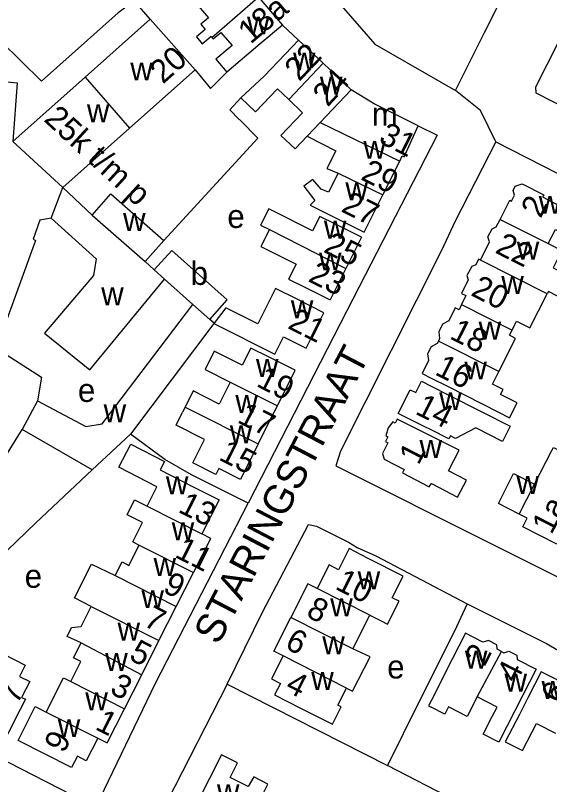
# Model space of a CAD drawing. Extents: x 159700 to 161346, y 381730 to 382922.
# Drawn here: x 160928.7 to 161020.3, y 382436.1 to 382568 of the extents above; entities that cross this region are included whole.
import ezdxf

# ---------------------------------------------------------------- set-up
doc = ezdxf.new("R2010")
doc.units = 0
for name, color, linetype in [('BLT_Basislijn', 7, 'Continuous'), ('BLT_Bebouwing', 7, 'Continuous'), ('BLT_Centroide', 7, 'Continuous'), ('BLT_Huisnummer', 7, 'Continuous'), ('BLT_Huisnummer_ tussenligend', 7, 'Continuous'), ('BLT_Huisnummer_reeks', 7, 'Continuous'), ('BLT_Onderverdeling_panden', 7, 'Continuous'), ('BLT_Straatnaam', 7, 'Continuous')]:
    doc.layers.add(name, color=color, linetype=linetype)

msp = doc.modelspace()

# ---------------------------------------------------------------- linework, layer by layer
at = {"layer": 'BLT_Basislijn'}
for p, q in [((160974.51, 382566.37), (160977.27, 382563.79)), ((161007.45, 382561.69), (161009.16, 382565.09)), ((161004.18, 382555.15), (161007.45, 382561.69)), ((160970.27, 382546.97), (160954.17, 382529.44)), ((160932.23, 382481.02), (160941.86, 382490.1)), ((160932.23, 382481.02), (160912.18, 382461.91)), ((160965.01, 382453.32), (160992.5, 382439.39))]:
    msp.add_line(p, q, dxfattribs=at)
for points in [[(161009.16, 382565.09), (161014.49, 382575.65), (161032.79, 382593.12), (161036.12, 382596.65), (161036.59, 382596.65), (161044.04, 382603.72), (161044.42, 382604.08)], [(160951.83, 382567.37), (160949.25, 382570.37), (160948.92, 382570.37), (160946.35, 382568.47), (160933.21, 382556.75), (160926.24, 382563.59)], [(160983.2, 382571.05), (160984.24, 382570.15), (160990.35, 382563.1), (161004.18, 382555.15)], [(161024.71, 382568.32), (161023.67, 382567.09), (161017.93, 382555.74), (161017.98, 382554.76), (161074.53, 382525.9), (161075.55, 382526.06), (161075.87, 382526.38), (161077.62, 382529.86)], [(160959.55, 382558.7), (160962.18, 382555.47), (160964.96, 382558.3)], [(160919.62, 382557.35), (160929.02, 382556.44), (160928.26, 382546.4)], [(161011.13, 382546.35), (161008.45, 382551.7), (161004.18, 382555.15)], [(160970.27, 382546.97), (160967.2, 382550.09), (160967.09, 382550.2), (160965.47, 382551.85), (160967.35, 382553.88)], [(160997.77, 382549.07), (161001.05, 382547.46), (160985.55, 382517.37), (160968.62, 382484.37)], [(161011.13, 382546.35), (161004.14, 382532.72), (161001.78, 382527.68), (160984.45, 382493.29), (160983.66, 382490.77), (161037.03, 382464.02), (161097.28, 382433.33), (161117.83, 382422.87), (161120.84, 382421.08), (161151.41, 382405.63), (161152.84, 382405.02), (161153.31, 382404.99), (161153.57, 382405.21), (161167.8, 382433.33), (161179.15, 382454.6), (161181.26, 382459.06), (161181.21, 382459.73), (161169.51, 382465.52), (161164.37, 382468.48), (161163.6, 382468.73), (161139.77, 382480.75)], [(161011.13, 382546.35), (161059.35, 382521.71), (161069.03, 382516.96), (161080.74, 382510.81), (161104.09, 382499.08), (161138.78, 382481.25), (161139.77, 382480.75)], [(160934.87, 382533.23), (160932.92, 382532.91), (160931.78, 382529.63), (160932.15, 382529.42), (160927.26, 382515.85), (160921.38, 382518.08)], [(160918.77, 382514.15), (160926.98, 382509.98), (160933.19, 382505.98), (160932.52, 382501.95)], [(160919.1, 382489.6), (160924.73, 382488.77), (160929.87, 382497)], [(160968.62, 382484.37), (160958.93, 382489.25), (160954.36, 382491.88), (160948.48, 382496.22)], [(160925.44, 382441), (160942.54, 382432.23), (160952.75, 382453.52), (160968.62, 382484.37)], [(160965.01, 382453.32), (160971.12, 382465.68), (160978.98, 382480.7), (160980.37, 382480.41), (160985.86, 382477.68), (160987.34, 382476.75), (160990.51, 382475.36), (161006.2, 382467.14)], [(161006.2, 382467.14), (161004, 382462.43), (160997.96, 382450.36), (160992.5, 382439.39)], [(161006.2, 382467.14), (161019.79, 382460.32), (161025.02, 382457.3), (161053.5, 382442.94), (161053.96, 382442.53), (161071.63, 382433.33), (161121.07, 382408.34)], [(160965.01, 382453.32), (160954.82, 382433.33), (160951.71, 382427.25), (160951.57, 382426.07), (160951.73, 382425.91), (161001.45, 382400.93), (161003.57, 382399.63), (161024.09, 382389.46), (161033.76, 382384.37), (161056.56, 382372.91)], [(161070.21, 382399.65), (161041.47, 382414.49), (161034.11, 382417.92), (161004.24, 382433.33), (160992.5, 382439.39)]]:
    msp.add_lwpolyline(points, dxfattribs=at)
at = {"layer": 'BLT_Bebouwing'}
for p, q in [((160970.39, 382571.19), (160974.51, 382566.37)), ((160940.68, 382557.44), (160951.83, 382567.37)), ((160951.83, 382567.37), (160959.55, 382558.7)), ((160981.47, 382559.81), (160977.27, 382563.79)), ((160986.28, 382555.24), (160981.47, 382559.81)), ((160959.55, 382558.7), (160948.26, 382548.66)), ((160928.26, 382546.4), (160940.68, 382557.44)), ((160948.26, 382548.66), (160936.84, 382538.5)), ((160936.84, 382538.5), (160928.26, 382546.4)), ((160991.72, 382537.23), (160994.62, 382543.03)), ((160934.87, 382533.23), (160936.84, 382538.5)), ((160941.9, 382533.77), (160945.07, 382537.4)), ((160945.07, 382537.4), (160954.17, 382529.44)), ((160988.54, 382530.86), (160991.72, 382537.23)), ((160954.17, 382529.44), (160951, 382525.81)), ((160988.09, 382529.97), (160985.41, 382524.6)), ((160952.52, 382524.37), (160951, 382525.81)), ((160985.41, 382524.6), (160982.72, 382519.24)), ((160941.46, 382507.22), (160954.3, 382522.78)), ((160954.3, 382522.78), (160959.15, 382518.46)), ((161016.95, 382514.44), (161019.9, 382520.27)), ((160962.06, 382515.86), (160965.06, 382519.22)), ((160962.76, 382515.19), (160948.48, 382496.22)), ((160962.78, 382515.22), (160962.06, 382515.86)), ((160933.71, 382513.56), (160941.46, 382507.22)), ((160932.52, 382501.95), (160929.87, 382497)), ((160957.83, 382500.86), (160957.4, 382500)), ((160973.1, 382500), (160973.64, 382501.07)), ((160970.37, 382494.53), (160973.1, 382500)), ((160941.86, 382490.1), (160929.87, 382497)), ((160948.48, 382496.22), (160941.86, 382490.1)), ((160948.86, 382477.75), (160949.95, 382477.19)), ((160956.29, 382466.64), (160959.25, 382472.49)), ((160953.33, 382460.8), (160956.29, 382466.64)), ((160986.56, 382459.41), (160989.48, 382465.18)), ((160950.38, 382454.95), (160953.33, 382460.8)), ((160934, 382448.55), (160936.96, 382454.4)), ((160936.96, 382454.4), (160938.2, 382453.78)), ((160947.42, 382449.11), (160950.38, 382454.95)), ((160932.12, 382449.51), (160934, 382448.55))]:
    msp.add_line(p, q, dxfattribs=at)
for points in [[(160959.36, 382570.44), (160961.81, 382567.58), (160960.54, 382566.5), (160961.28, 382565.62), (160959.76, 382564.34), (160960.76, 382563.15), (160962.28, 382564.44), (160962.43, 382564.26)], [(160974.51, 382566.37), (160970.69, 382563.14), (160964.96, 382558.3)], [(160962.43, 382564.26), (160962.64, 382564.02), (160963.96, 382565.12)], [(160963.96, 382565.12), (160965.87, 382562.89), (160963.08, 382560.5), (160964.96, 382558.3)], [(160977.27, 382563.79), (160973.83, 382560.17), (160971.39, 382557.59), (160967.35, 382553.88)], [(160967.35, 382553.88), (160969.87, 382551.49), (160973.64, 382555.46), (160975.59, 382553.6)], [(160997.77, 382549.07), (160990.24, 382552.87), (160986.28, 382555.24)], [(160975.59, 382553.61), (160977.98, 382551.34), (160974.26, 382547.42), (160976.68, 382545.12), (160978.76, 382547.32)], [(160994.62, 382543.03), (160995.07, 382543.92), (160995.41, 382543.75), (160997.77, 382549.07)], [(160978.76, 382547.32), (160978.86, 382547.23), (160983.67, 382544.81), (160982.12, 382541.75), (160984.07, 382540.98)], [(160984.07, 382540.98), (160982.42, 382537.71), (160981.14, 382538.24), (160979.71, 382539.91), (160978.19, 382538.73), (160980.08, 382536.3), (160979.28, 382535.49), (160984.07, 382533.1), (160988.54, 382530.86)], [(161011.84, 382533.05), (161013.49, 382536.33), (161013.78, 382536.18), (161014.28, 382537.17), (161014.07, 382538.01), (161014.44, 382538.74), (161015.62, 382539.12), (161019.32, 382537.28), (161019.11, 382536.9), (161028.1, 382532.15)], [(160941.9, 382533.77), (160936.84, 382538.5)], [(160975.17, 382533.37), (160972.17, 382534.88), (160970.75, 382532.08), (160972.27, 382531.31)], [(160988.09, 382529.97), (160983.62, 382532.21), (160980.94, 382533.55), (160979.69, 382531.08), (160977.49, 382532.19), (160975.17, 382533.37)], [(160934.87, 382533.23), (160942.58, 382526.29), (160942.12, 382523.41), (160933.71, 382513.56)], [(161008.45, 382526.05), (161010.04, 382529.2), (161009.75, 382530.04), (161010.46, 382531.45), (161011.18, 382531.74), (161011.84, 382533.05)], [(161020.1, 382528.88), (161021.33, 382531.32), (161024.39, 382529.77), (161024.67, 382530.32), (161026.69, 382529.3), (161028.1, 382532.15)], [(160972.27, 382531.31), (160970.8, 382528.41)], [(160970.8, 382528.41), (160976.85, 382525.35), (160975.57, 382522.81), (160978.25, 382521.47), (160982.72, 382519.24)], [(161020.1, 382528.88), (161022.43, 382527.7), (161020.92, 382524.73), (161024.68, 382522.82), (161022.89, 382519.27), (161020.11, 382520.68), (161019.9, 382520.27)], [(160965.06, 382519.22), (160955.52, 382527.73), (160952.52, 382524.37)], [(161008.45, 382526.05), (161008.14, 382526.21), (161007.67, 382525.26), (161006.97, 382524.99), (161006.16, 382523.43), (161006.36, 382522.65), (161005.21, 382520.35), (161005.96, 382519.97), (161005.21, 382518.43)], [(160981.63, 382517.04), (160977.15, 382519.28), (160973.33, 382521.2), (160970.29, 382515.12), (160964.78, 382517.87), (160962.78, 382515.22)], [(160932.52, 382501.95), (160940.79, 382497.53), (160943.58, 382497.96), (160959.15, 382518.46)], [(161005.21, 382518.43), (161004.79, 382517.55), (161004.14, 382517.87), (161003.02, 382515.67), (161001.96, 382515.05), (161001.32, 382513.78), (161001.47, 382512.59), (161001.26, 382512.18)], [(160962.76, 382515.19), (160973.23, 382509.95), (160974.7, 382512.9), (160978.58, 382510.96), (160981.63, 382517.04)], [(161013.88, 382514.06), (161014.66, 382515.6), (161016.95, 382514.44)], [(161011.62, 382506.95), (161014.5, 382512.64), (161013.43, 382513.18), (161013.88, 382514.06)], [(161001.26, 382512.18), (161001.05, 382511.77), (161000, 382511.17), (160999.39, 382509.97), (160999.58, 382508.86), (160998.45, 382506.62), (161000, 382505.84), (161002.91, 382504.36), (161011.55, 382500), (161013.46, 382499.03), (161014.76, 382501.6), (161011.92, 382503.04), (161012.34, 382503.86), (161010.52, 382504.78), (161011.62, 382506.95)], [(160973.64, 382501.07), (160976.68, 382507.16), (160972.21, 382509.4), (160969.07, 382510.97), (160967.58, 382508.02), (160962.83, 382510.42), (160961.26, 382507.32), (160965.57, 382505.14)], [(160965.57, 382505.14), (160963.67, 382501.37), (160959.23, 382503.62), (160957.83, 382500.86)], [(160994.47, 382500), (160996.41, 382503.84), (160997.37, 382503.35), (160998.35, 382505.29), (161000, 382504.46), (161002.81, 382503.04), (161008.82, 382500), (161013.58, 382497.6), (161012.23, 382494.97), (161007.68, 382497.31), (161004.21, 382495.47), (161003.32, 382495.93), (161003.05, 382495.39), (161000, 382496.93)], [(160970.37, 382494.53), (160967.3, 382488.45), (160963.61, 382490.32), (160963.1, 382489.29), (160959.14, 382491.27), (160961.15, 382495.29), (160956.28, 382497.75), (160957.4, 382500)], [(161000, 382496.93), (160998.82, 382497.53), (160994.36, 382499.78), (160994.47, 382500)], [(161000, 382495.87), (160998.65, 382496.55), (160994.19, 382498.8), (160993.83, 382498.11), (160993.46, 382498.3), (160992.63, 382497.3), (160992.27, 382495.91), (160992.59, 382495.74), (160992.18, 382494.93), (160992.61, 382494.71), (160991.67, 382492.87), (160991.97, 382491.93), (160995.4, 382490.16), (160995.09, 382489.56), (160999.7, 382487.18), (161000, 382487.67)], [(161000, 382487.67), (161000.05, 382487.76), (161004.56, 382485.43), (161006.05, 382488.33), (161003, 382489.92), (161004.81, 382493.44), (161000, 382495.87)], [(160951.29, 382483.86), (160952.98, 382487.19), (160946.45, 382490.58), (160948.49, 382494.48), (160954.27, 382491.54), (160953.52, 382490.07), (160959.18, 382487.18), (160963.64, 382484.93), (160960.69, 382479.1)], [(161017.74, 382487.61), (161020.7, 382493.39), (161020.98, 382493.95), (161028.16, 382490.32), (161026.07, 382486.23)], [(161015.12, 382482.5), (161011.55, 382484.33), (161014.16, 382489.44), (161017.74, 382487.61)], [(161026.07, 382486.23), (161023.82, 382481.81), (161021.54, 382477.36), (161015.75, 382480.34), (161016.5, 382481.8), (161015.12, 382482.5)], [(160948.86, 382477.75), (160950.53, 382481.06), (160947.86, 382482.36), (160949.12, 382484.94), (160951.29, 382483.86)], [(160959.25, 382472.49), (160962.21, 382478.33), (160960.69, 382479.1)], [(160945.81, 382471.95), (160947, 382474.29), (160948.18, 382473.69), (160949.95, 382477.19)], [(160989.48, 382465.18), (160991.34, 382464.26), (160992.55, 382463.63), (160994.52, 382467.55), (160993.32, 382468.16), (160995.21, 382471.88), (160989.23, 382474.91), (160985.94, 382476.58), (160985.08, 382474.88), (160984.11, 382472.97), (160982.51, 382473.78), (160980.47, 382469.74)], [(160941.72, 382466.68), (160938.85, 382468.13), (160941.78, 382473.93), (160945.81, 382471.95)], [(160980.47, 382469.74), (160978.87, 382470.55), (160975.94, 382464.78)], [(160939.97, 382460.4), (160937.58, 382461.54), (160938.34, 382463.06), (160939.98, 382463.23), (160941.72, 382466.68)], [(160974.61, 382458.18), (160973.01, 382458.99), (160975.94, 382464.78)], [(161012.05, 382458.95), (161011.32, 382459.32), (161011.29, 382460.1), (161009.83, 382460.85), (161008.89, 382460.55), (161005.92, 382462.07), (161003.64, 382457.62), (161000, 382450.5)], [(160923.33, 382461.52), (160927.14, 382459.57), (160926.6, 382458.52), (160930.4, 382456.57), (160929.43, 382454.68), (160931.17, 382453.79), (160929.78, 382451.08), (160930.43, 382450.75), (160929.54, 382449), (160925.44, 382441)], [(160938.2, 382453.78), (160939.95, 382457.23), (160938.69, 382457.87), (160939.97, 382460.4)], [(160985.49, 382452.67), (160986.55, 382452.13), (160989.54, 382458.03), (160986.56, 382459.41)], [(160974.61, 382458.18), (160972.63, 382454.26), (160974.17, 382453.48), (160973.17, 382451.5), (160977.63, 382449.24), (160983.08, 382446.48), (160984.58, 382449.46), (160984.01, 382449.75), (160985.49, 382452.67)], [(161012.05, 382458.95), (161012.48, 382458.73), (161013.35, 382459.01), (161014.73, 382458.31), (161014.76, 382457.55), (161018.02, 382455.89), (161015.74, 382451.44), (161011.62, 382443.39), (161008.93, 382444.76), (161010.47, 382447.77), (161011.31, 382449.4), (161007.88, 382451.16)], [(161025.13, 382452.33), (161018.9, 382455.47), (161016.62, 382451.02), (161015.14, 382448.16), (161012.73, 382443.46), (161015.68, 382441.95), (161018.06, 382446.6), (161021.34, 382444.93)], [(161000, 382450.5), (160999.56, 382449.63), (161000, 382449.41)], [(161007.88, 382451.16), (161006.18, 382447.82), (161002.98, 382449.45), (161002.34, 382448.21), (161000, 382449.41)], [(160942.84, 382444.08), (160940.88, 382440.2), (160939.34, 382440.98), (160938.35, 382439.02), (160929.18, 382443.67), (160931.43, 382448.13), (160932.12, 382449.51)], [(160942.84, 382444.08), (160944.46, 382443.26), (160947.42, 382449.11)], [(160968.61, 382435.77), (160965.52, 382437.34), (160966.79, 382439.83), (160964.06, 382441.22), (160960.05, 382433.33), (160957.95, 382429.22), (160963.78, 382426.25)], [(160974.43, 382432.81), (160973.4, 382433.33), (160971.15, 382434.48), (160972.03, 382436.21), (160969.61, 382437.44), (160968.61, 382435.77)]]:
    msp.add_lwpolyline(points, dxfattribs=at)
at = {"layer": 'BLT_Onderverdeling_panden'}
for p, q in [((160962.43, 382564.26), (160970.39, 382571.19)), ((160981.47, 382559.81), (160975.59, 382553.61)), ((160940.68, 382557.44), (160948.26, 382548.66)), ((160986.28, 382555.24), (160980.98, 382549.65)), ((160980.98, 382549.65), (160978.76, 382547.32)), ((160980.98, 382549.65), (160994.62, 382543.03)), ((160984.07, 382540.98), (160991.72, 382537.23)), ((160941.9, 382533.77), (160951, 382525.81)), ((161011.84, 382533.05), (161020.1, 382528.88)), ((160972.27, 382531.31), (160985.41, 382524.6)), ((161019.9, 382520.27), (161008.45, 382526.05)), ((160952.52, 382524.37), (160954.3, 382522.78)), ((160959.15, 382518.46), (160962.06, 382515.86)), ((161005.21, 382518.43), (161013.88, 382514.06)), ((160962.78, 382515.22), (160962.76, 382515.19)), ((161011.62, 382506.95), (161001.26, 382512.18)), ((160965.57, 382505.14), (160973.64, 382501.07)), ((160957.83, 382500.86), (160970.37, 382494.53)), ((161015.12, 382482.5), (161017.74, 382487.61)), ((160951.29, 382483.86), (160960.69, 382479.1)), ((160949.95, 382477.19), (160959.25, 382472.49)), ((160945.81, 382471.95), (160956.29, 382466.64)), ((160989.48, 382465.18), (160980.47, 382469.74)), ((160941.72, 382466.68), (160953.33, 382460.8)), ((160986.56, 382459.41), (160975.94, 382464.78)), ((160939.97, 382460.4), (160950.38, 382454.95)), ((160985.49, 382452.67), (160974.61, 382458.18)), ((161007.88, 382451.16), (161012.05, 382458.95)), ((160938.2, 382453.78), (160947.42, 382449.11)), ((160934, 382448.55), (160942.84, 382444.08))]:
    msp.add_line(p, q, dxfattribs=at)

# ---------------------------------------------------------------- texts
at = {"layer": 'BLT_Centroide'}
for s, p in [('w', (160968.44, 382564.75)), ('w', (160976.32, 382558.59)), ('w', (160948.42, 382556.87)), ('w', (160980.94, 382554.42)), ('w', (160940.98, 382549.71)), ('m', (160989.84, 382549.12)), ('w', (160988.38, 382543.44)), ('w', (160985.31, 382536.31)), ('w', (161018.45, 382534)), ('e', (160965.06, 382531.57)), ('w', (160947.18, 382531.06)), ('w', (160981.62, 382529.75)), ('w', (161014.69, 382526.16)), ('w', (160980.78, 382524.28)), ('b', (160958.77, 382521.81)), ('w', (161012.04, 382520.25)), ('w', (160943.43, 382518.32)), ('w', (160975.95, 382516.09)), ('w', (161008.16, 382512.41)), ('w', (160969.97, 382506.03)), ('w', (161005.71, 382505.59)), ('e', (160939.44, 382501.74)), ('w', (160966.44, 382499.84)), ('w', (161001.39, 382500.34)), ('w', (160943.85, 382498.25)), ('w', (160965.48, 382494.66)), ('w', (160998.02, 382492.12)), ('w', (160954.52, 382485.89)), ('w', (161014.64, 382485.97)), ('w', (160955.53, 382478.03)), ('w', (160952.41, 382471.91)), ('e', (160930.31, 382469.87)), ('w', (160987.41, 382469.59)), ('w', (160950.33, 382466.38)), ('w', (160982.71, 382464.97)), ('w', (160946.23, 382460.81)), ('w', (160981.34, 382458.47)), ('w', (160944.12, 382455.59)), ('w', (161005.8, 382456)), ('e', (160992.47, 382454.31)), ('w', (160979.45, 382452.34)), ('w', (161012.59, 382452.05)), ('w', (161018.94, 382450.8)), ('w', (160940.71, 382448.84)), ('w', (160935.98, 382444.25)), ('w', (160963.28, 382433.09))]:
    msp.add_text(s, height=4, dxfattribs=at).set_placement(p)
at = {"layer": 'BLT_Huisnummer'}
for s, rotation, p in [('20', 41.6622, (160954.01, 382556.15)), ('22', 46.4931, (160977.38, 382556.57)), ('24', 47.3238, (160982.27, 382552.21)), ('31', 333.1155, (160990.81, 382546.32)), ('27', 333.4247, (160984.4, 382534.47)), ('2', 63.1917, (161018.78, 382533.11)), ('22', 333.1874, (161010.8, 382527.41)), ('23', 333.4196, (160978.76, 382522.5)), ('21', 333.4093, (160975.25, 382514.45)), ('18', 333.1965, (161003.01, 382512.68)), ('19', 333.2288, (160969.86, 382504.52)), ('14', 333.2024, (160997.1, 382499.78)), ('15', 333.1633, (160963.4, 382491.91)), ('1', 62.7478, (160997.85, 382490.77)), ('13', 333.1579, (160956.45, 382482.95)), ('1a', 62.7944, (161020.65, 382478.86)), ('10', 333.1292, (160983.38, 382469.75)), ('9', 333.1622, (160953.81, 382469.25)), ('6', 333.1313, (160974.75, 382459.58)), ('5', 332.4305, (160948.02, 382457.65)), ('2', 62.8814, (161009.17, 382456.23)), ('4', 333.1326, (160974.81, 382452.24)), ('7', 62.8881, (160929.04, 382449.74)), ('6', 62.8826, (161022.21, 382449.78)), ('1', 333.1643, (160942.21, 382445.68)), ('9', 63.1576, (160937.04, 382441.35))]:
    msp.add_text(s, height=4, rotation=rotation, dxfattribs=at).set_placement(p)
at = {"layer": 'BLT_Huisnummer_ tussenligend'}
for s, rotation, p in [('18a', 40.2047, (160969.03, 382562.98)), ('29', 333.4247, (160987.76, 382539.97)), ('25', 333.4196, (160981.39, 382527.53)), ('20', 333.1965, (161006.64, 382520.09)), ('16', 333.2024, (161000.47, 382506.53)), ('17', 333.1633, (160966.59, 382498.32)), ('11', 333.1622, (160955.87, 382475.21)), ('8', 333.1313, (160978.39, 382465.03)), ('7', 332.4305, (160950.48, 382463.48)), ('4', 62.8814, (161014.61, 382453.36)), ('3', 333.1643, (160944.72, 382451.86))]:
    msp.add_text(s, height=4, rotation=rotation, dxfattribs=at).set_placement(p)
at = {"layer": 'BLT_Huisnummer_reeks'}
msp.add_text('25k t/m p', height=4, rotation=317.362, dxfattribs=at).set_placement((160933.44, 382550.02))
at = {"layer": 'BLT_Straatnaam'}
msp.add_text('STARINGSTRAAT', height=4.9999, rotation=62.3828, dxfattribs=at).set_placement((160963.52, 382459.89))

doc.saveas('drawing.dxf')
